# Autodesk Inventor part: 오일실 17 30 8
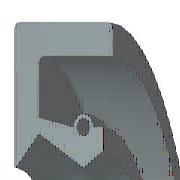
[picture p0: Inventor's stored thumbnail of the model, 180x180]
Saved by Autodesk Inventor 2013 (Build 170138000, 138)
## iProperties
Created: 2012-02
Part Number: 오일실 17 30 8
Material: 고무
Description: 오일-실
Document SubType Name: Modeling
Standard: KS B 2804
Designer: mduedu
Standards Organization: KS
Language: ko-KR
Size Designation: D - 17 30 8
Categories: <MemberInstance><Categories><Category DisplayName="샤프트 부품" InternalName="7f7aeb1f-a693-4053-b835-cee3144e0d98" Mnemonic="SHFT"><Category DisplayName="실링" Intern
Density: 0.93 g/cm^3
Mass: 2.05797 g
Surface Area: 29.3036 cm^2
Volume: 2.21288 cm^3
IsCustomPart: 1
Author: mduedu
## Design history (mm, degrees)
revolve "본체" stored, may be unused: angle "d17" = 90 deg
revolve "스프링1" stored, may be unused: angle "d18" = 90 deg
body "Solid1"
sketch "스케치1"
  geometry: L1 (0, 15)-(8, 15); L2 (8, 13.25)-(1.75, 13.25); L3 (1.75, 10.25)-(4.9, 8.5); L4 (4.9, 8.5)-(0, 8.5); L5 (0, 0)-(9.586, 0) reference; L6 (4.9, 8.5)-(6.3, 9.375); L7 (0, 18)-(0, -3) reference; L8 (-1.941, 0)-(11.507, 0) reference; L9 (4.2, 10.6)-(1.75, 11.21); L10 (1.75, 11.21)-(1.75, 13.25); L11 (0, 15)-(0, 8.588); L12 (4.9, 8.5)-(0, 8.5); L13 (1.75, 10.25)-(0.152, 8.528); L14 (8, 15)-(8, 13.25); L15 (5.6, 10.6)-(6.3, 10.6); L16 (6.3, 10.6)-(6.3, 9.375); C1 r 0.455 at (4.9, 10.6); A1 r 0.7 centre (4.9, 10.6) between (5.6, 10.6) and (4.2, 10.6); A2 r 0.088 centre (0.088, 8.588) between (0, 8.588) and (0.152, 8.528); 1 further point
  constraints: 28 end point, 5 horizontal alignment, 5 point on line, 4 point on circle, 4 vertical alignment, 3 centre point, 3 tangent, 2 collinear, 2 horizontal, 2 perpendicular, 1 coincident, 1 parallel
  dimensions: "d0" = 30 diameter of L1 L5 (= SD2); "d1" = 1.75 distance of L1.end L2.start (= SD); "d2" = 0.91 diameter of C1 (= SPDI); "d3" = 1.4 diameter of A1 (= SPDA); "d4" = 17 diameter of L3.end L5 (= NND); "d5" = 20.5 diameter of L3.start L5 (= TKDM); "d7" = 22.42 diameter of L9.end L5 (= TKDM + 0.24 x SWDT); "d8" = 1.75 distance between parallel lines of L11 L10 (= SD); "d9" = 4.9 distance from line of L11 C1.centre (= SPDST); "d10" = 21.2 diameter of C1.centre L5 (= HLDM); "d11" = 0.0875 radius of A2 (= 0.25 x LAB); "d12" = 6.3 distance between parallel lines of L11 L16 (= SDI); "d13" = 18.75 diameter of L6.end L5 (= ABDM); "d14" = 8 distance from line of L11 L1.end (= SWDT)
fillet "모깎기1" dims "d6" = 0.3 (= RR)
other parameters: "SD2" = 30 [user parameter; used in 1 equation term], "SWDT" = 8 [user parameter; used in 2 equation terms], "RR" = 0.3 [user parameter; used in 1 equation term], "SD" = 1.75 [user parameter; used in 2 equation terms], "NND" = 17 [user parameter; used in 1 equation term], "SPDA" = 1.4 [user parameter; used in 1 equation term], "SPDI" = 0.91 [user parameter; used in 1 equation term], "TKDM" = 20.5 [user parameter; used in 2 equation terms], "HLDM" = 21.2 [user parameter; used in 1 equation term], "ABDM" = 18.75 [user parameter; used in 1 equation term], "SDI" = 6.3 [user parameter; used in 1 equation term], "SPDST" = 4.9 [user parameter; used in 1 equation term], "LAB" = 0.35 [user parameter; used in 1 equation term], "d15" = 0, "d16" = 0, "d19" = 0
